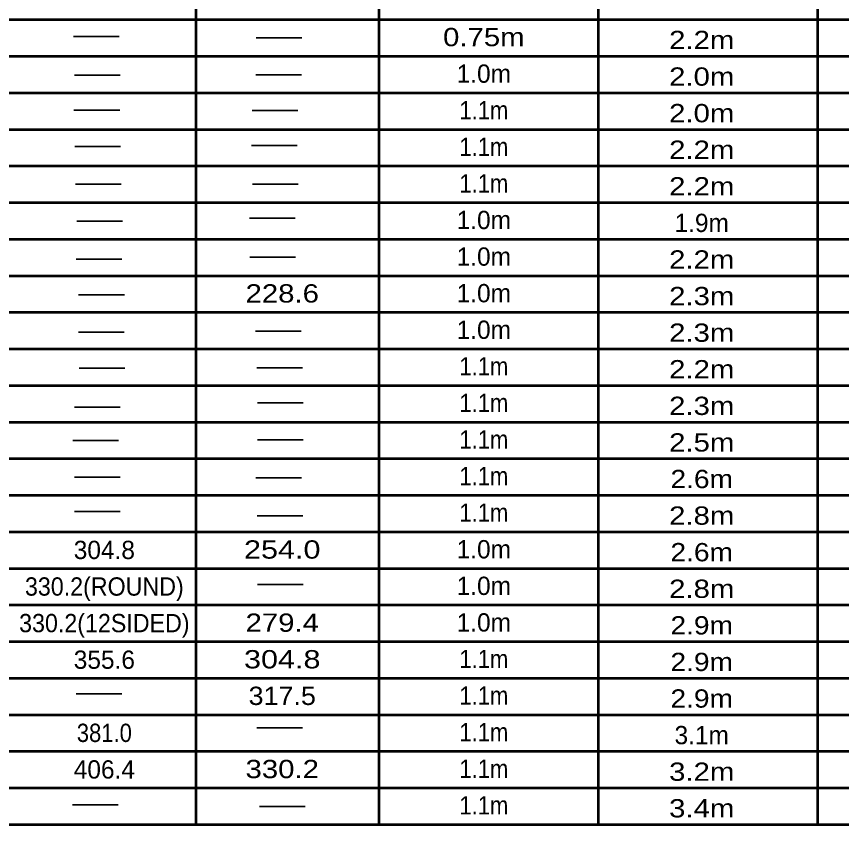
# Model space of a CAD drawing. Extents: x -711 to 145, y 25 to 569.
# Drawn here: x -112 to 13, y 281.9 to 404.4 of the extents above; entities that cross this region are included whole.
import ezdxf
from ezdxf.enums import TextEntityAlignment as Align

# ---------------------------------------------------------------- set-up
doc = ezdxf.new("R2010")
doc.units = 0
doc.header["$LTSCALE"] = 1.1
doc.layers.add('1', color=7, linetype='Continuous', lineweight=53)

msp = doc.modelspace()

# ---------------------------------------------------------------- linework, layer by layer
at = {"layer": '1'}
for p, q in [((-57.107, 521.717), (-57.107, 281.939)), ((-84.827, 514.094), (-84.827, 281.939)), ((-23.843, 509.936), (-23.843, 281.939)), ((9.421, 509.936), (9.421, 281.939)), ((-251.147, 403.907), (109.194, 403.907)), ((-251.147, 398.363), (109.194, 398.363)), ((-251.147, 392.819), (109.194, 392.819)), ((-251.147, 387.275), (109.194, 387.275)), ((-251.147, 381.731), (109.194, 381.731)), ((-251.147, 376.187), (109.194, 376.187)), ((-251.147, 370.643), (109.194, 370.643)), ((-251.147, 365.099), (109.194, 365.099)), ((-251.147, 359.555), (109.194, 359.555)), ((-251.147, 354.011), (109.194, 354.011)), ((-251.147, 348.467), (109.194, 348.467)), ((-251.147, 342.923), (109.194, 342.923)), ((-251.147, 337.379), (109.194, 337.379)), ((-251.147, 331.835), (109.194, 331.835)), ((-251.147, 326.291), (109.194, 326.291)), ((-251.147, 320.747), (109.194, 320.747)), ((-251.147, 315.203), (109.194, 315.203)), ((-251.147, 309.659), (109.194, 309.659)), ((-251.147, 304.115), (109.194, 304.115)), ((-251.147, 298.571), (109.194, 298.571)), ((-251.147, 293.027), (109.194, 293.027)), ((-251.147, 287.483), (109.194, 287.483)), ((-251.147, 281.939), (109.213, 281.939))]:
    msp.add_line(p, q, dxfattribs=at)
at = {"layer": '1', "lineweight": 35}
for p, q in [((-103.377, 401.327), (-96.447, 401.327)), ((-75.696, 401.15), (-68.766, 401.15)), ((-103.234, 395.508), (-96.304, 395.508)), ((-75.734, 395.542), (-68.803, 395.542)), ((-103.305, 390.207), (-96.375, 390.207)), ((-76.294, 390.134), (-69.364, 390.134)), ((-103.164, 384.67), (-96.234, 384.67)), ((-76.399, 384.811), (-69.469, 384.811)), ((-103.056, 378.949), (-96.127, 378.949)), ((-76.256, 378.986), (-69.326, 378.986)), ((-102.88, 373.371), (-95.95, 373.371)), ((-76.715, 373.823), (-69.785, 373.823)), ((-76.646, 367.902), (-69.716, 367.902)), ((-102.955, 367.623), (-96.025, 367.623)), ((-102.598, 362.183), (-95.668, 362.183)), ((-102.635, 356.54), (-95.705, 356.54)), ((-75.81, 356.685), (-68.88, 356.685)), ((-102.498, 351.071), (-95.568, 351.071)), ((-75.603, 351.152), (-68.673, 351.152)), ((-103.234, 345.197), (-96.304, 345.197)), ((-75.496, 345.857), (-68.566, 345.857)), ((-75.49, 340.227), (-68.56, 340.227)), ((-103.484, 340.116), (-96.554, 340.116)), ((-103.234, 334.548), (-96.303, 334.548)), ((-75.73, 334.449), (-68.8, 334.449)), ((-103.234, 329.371), (-96.303, 329.371)), ((-75.555, 328.735), (-68.625, 328.735)), ((-75.48, 318.29), (-68.55, 318.29)), ((-102.987, 301.715), (-96.057, 301.715)), ((-75.585, 296.566), (-68.655, 296.566)), ((-103.514, 284.929), (-96.584, 284.929)), ((-75.195, 284.683), (-68.265, 284.683))]:
    msp.add_line(p, q, dxfattribs=at)

# ---------------------------------------------------------------- texts
at = {"layer": '1'}
for s, width, p in [('0.75m', 1.2, (-41.173, 399.879)), ('2.2m', 1.2, (-8.145, 399.436)), ('2.0m', 1.2, (-8.145, 393.892)), ('1.1m', 0.9, (-41.173, 388.791)), ('2.0m', 1.2, (-8.145, 388.348)), ('1.1m', 0.9, (-41.173, 383.247)), ('2.2m', 1.2, (-8.145, 382.804)), ('1.1m', 0.9, (-41.173, 377.703)), ('2.2m', 1.2, (-8.145, 377.26)), ('2.2m', 1.2, (-8.145, 366.172)), ('228.6', 1.2, (-71.732, 361.034)), ('2.3m', 1.2, (-8.145, 360.628)), ('2.3m', 1.2, (-8.145, 355.084)), ('1.1m', 0.9, (-41.173, 349.983)), ('2.2m', 1.2, (-8.145, 349.54)), ('1.1m', 0.9, (-41.173, 344.439)), ('2.3m', 1.2, (-8.145, 343.996)), ('1.1m', 0.9, (-41.173, 338.895)), ('2.5m', 1.2, (-8.145, 338.452)), ('1.1m', 0.9, (-41.173, 333.351)), ('2.6m', 1.15, (-8.144, 332.908)), ('1.1m', 0.9, (-41.173, 327.807)), ('2.8m', 1.2, (-8.145, 327.364)), ('254.0', 1.25, (-71.732, 322.226)), ('2.6m', 1.15, (-8.144, 321.82)), ('330.2(ROUND)', 0.95, (-98.699, 316.618)), ('2.8m', 1.2, (-8.145, 316.276)), ('330.2(12SIDED)', 0.95, (-98.699, 311.074)), ('279.4', 1.2, (-71.732, 311.138)), ('2.9m', 1.15, (-8.144, 310.732)), ('304.8', 1.25, (-71.732, 305.594)), ('1.1m', 0.9, (-41.173, 305.631)), ('2.9m', 1.15, (-8.144, 305.188)), ('317.5', 1.1, (-71.732, 300.05)), ('1.1m', 0.9, (-41.173, 300.087)), ('2.9m', 1.15, (-8.144, 299.644)), ('381.0', 0.9, (-98.699, 294.442)), ('1.1m', 0.9, (-41.173, 294.543)), ('330.2', 1.2, (-71.732, 288.962)), ('1.1m', 0.9, (-41.173, 288.999)), ('3.2m', 1.2, (-8.145, 288.556)), ('1.1m', 0.9, (-41.173, 283.455)), ('3.4m', 1.2, (-8.144, 283.012))]:
    msp.add_text(s, height=2.772, dxfattribs=dict(at, width=width)).set_placement(p, align=Align.CENTER)
for s, p in [('1.0m', (-41.173, 394.335)), ('1.0m', (-41.173, 372.159)), ('1.9m', (-8.144, 371.716)), ('1.0m', (-41.173, 366.615)), ('1.0m', (-41.173, 361.071)), ('1.0m', (-41.173, 355.527)), ('304.8', (-98.699, 322.162)), ('1.0m', (-41.173, 322.263)), ('1.0m', (-41.173, 316.719)), ('1.0m', (-41.173, 311.175)), ('355.6', (-98.699, 305.53)), ('3.1m', (-8.144, 294.1)), ('406.4', (-98.699, 288.898))]:
    msp.add_text(s, height=2.772, dxfattribs=at).set_placement(p, align=Align.CENTER)

doc.saveas('drawing.dxf')
